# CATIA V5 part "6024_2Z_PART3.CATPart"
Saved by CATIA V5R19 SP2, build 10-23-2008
Part number: 6024_2Z_PART3
Bounding box of the stored display mesh (mm): x 1.155 to 1.925, y -82.411 to 82.411, z -82.48 to 82.48
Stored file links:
  G:\EU_thinkMotion\CFAO_2010\MMS_groupe2\MMS_groupe2\OK\nrosalie\nrosalie_cfao_support_d_arme_legere_final\6024_2Z_PART3.CATPart
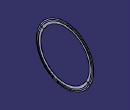
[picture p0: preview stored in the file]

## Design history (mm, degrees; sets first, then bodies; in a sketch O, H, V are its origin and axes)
Set1
  Point1: (0, 0, 0)
  Point2: (1, 0, 0)
  Point3: (0, 1, 0)
  Plane1: type 3Points, Element1 Point1, Element2 Point2, Element3 Point3
Body1 (main body)
  Sketch1 on Plane1, origin (0, 0, 0), H (1, 0, 0), V (0, 1, 0)
    point P1 (1.155, 69.5)
    point P2 (1.54, 69.5)
    line L1 (1.155, 69.5) -> (1.54, 69.5)
    point P3 (1.54, 69.5)
    point P4 (1.925, 76)
    line L2 (1.54, 69.5) -> (1.925, 76)
    point P5 (1.925, 76)
    point P6 (1.925, 79.2158)
    line L3 (1.925, 76) -> (1.925, 79.2158)
    point P7 (1.925, 79.2158)
    point P8 (1.54, 82.5)
    line L4 (1.925, 79.2158) -> (1.54, 82.5)
    point P9 (1.54, 82.5)
    point P10 (1.155, 82.5)
    line L5 (1.54, 82.5) -> (1.155, 82.5)
    point P11 (1.155, 82.5)
    point P12 (1.3475, 79.25)
    line L6 (1.155, 82.5) -> (1.3475, 79.25)
    point P13 (1.3475, 79.25)
    point P14 (1.155, 76)
    line L7 (1.3475, 79.25) -> (1.155, 76)
    point P15 (1.155, 76)
    point P16 (1.155, 69.5)
    line L8 (1.155, 76) -> (1.155, 69.5)
    point P17 (1.54, 0)
    point P18 (1.155, 0)
    axis line L9 (1.54, 0) -> (1.155, 0)
    point P19 (1.155, 69.5)
    point P20 (1.54, 69.5)
    point P21 (1.54, 69.5)
    point P22 (1.925, 76)
    point P23 (1.925, 76)
    point P24 (1.925, 79.2158)
    point P25 (1.925, 79.2158)
    point P26 (1.54, 82.5)
    point P27 (1.54, 82.5)
    point P28 (1.155, 82.5)
    point P29 (1.155, 82.5)
    point P30 (1.3475, 79.25)
    point P31 (1.3475, 79.25)
    point P32 (1.155, 76)
    point P33 (1.155, 76)
    point P34 (1.155, 69.5)
    coincidence: P19 P34, P20 P21, P22 P23, P24 P25, P26 P27, P28 P29, P30 P31, P32 P33
  Shaft1: profile Sketch1, axis Sketch1.L9, angle 0, second angle 360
